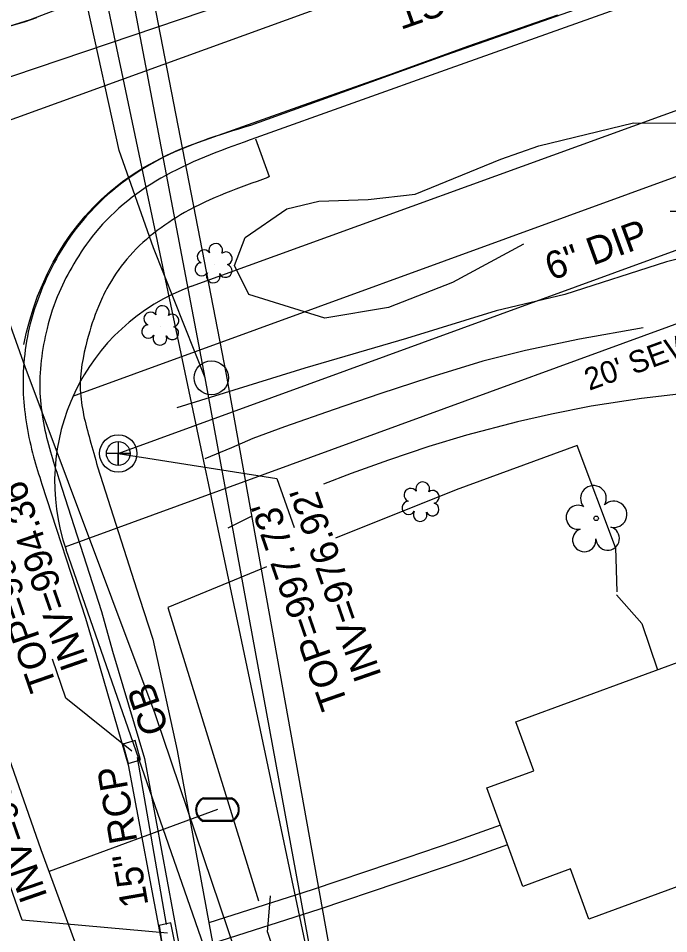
# Model space of a CAD drawing. Extents: x 1614427 to 1617186, y 896524 to 905462.
# Drawn here: x 1616382.3 to 1616476.2, y 903503 to 903635.2 of the extents above; entities that cross this region are included whole.
import ezdxf

# ---------------------------------------------------------------- set-up
doc = ezdxf.new("R2010")
doc.units = 0
for name, color, linetype in [('Exist Building', 7, 'Continuous'), ('Exist Horizontal Alignment', 7, 'Continuous'), ('Exist Other Culture Area Outline', 7, 'Continuous'), ('Exist Other Culture Fence Line', 7, 'Continuous'), ('Exist Other Culture Gate', 7, 'Continuous'), ('Exist Right of Way Easement Line', 7, 'Continuous'), ('Exist Right of Way Easement Line Text', 7, 'Continuous'), ('Exist Right of Way Line', 7, 'Continuous'), ('Exist Roads Curbs', 7, 'Continuous'), ('Exist Roads EOP', 7, 'Continuous'), ('Exist Roads EOP Other', 7, 'Continuous'), ('Exist Roads EOP Text', 7, 'Continuous'), ('Exist Roads Soil', 7, 'Continuous'), ('Exist Structure Minor Catch Basin', 7, 'Continuous'), ('Exist Structure Minor Catch Basin Leader', 7, 'Continuous'), ('Exist Structure Minor Catch Basin Text', 7, 'Continuous'), ('Exist Structure Minor Catch Basin Top Elevation', 7, 'Continuous'), ('Exist Structure Minor Pipes RCP 15 Inch', 7, 'Continuous'), ('Exist Structure Minor Pipes RCP 15 Inch Invert', 7, 'Continuous'), ('Exist Structure Minor Pipes RCP 15 Inch Text', 7, 'Continuous'), ('Exist Utilities Other Pole CELL', 7, 'Continuous'), ('Exist Utilities Sanitary Sewer Manhole CELL', 7, 'Continuous'), ('Exist Utilities Sanitary Sewer Manhole Leader', 7, 'Continuous'), ('Exist Utilities Sanitary Sewer Manhole Text', 7, 'Continuous'), ('Exist Utilities Sanitary Sewer UG Line', 7, 'Continuous'), ('Exist Utilities Sanitary Sewer UG Line Invert Elevation', 7, 'Continuous'), ('Exist Utilities Sanitary Sewer UG Line Text', 7, 'Continuous'), ('Exist Utilities Telephone UG FO SUE LOS B', 7, 'Continuous'), ('Exist Utilities Telephone UG FO SUE LOS D', 7, 'Continuous'), ('Exist Utilities TV UG FO Cable SUE LOS B', 7, 'Continuous'), ('Exist Utilities TV UG FO Cable SUE LOS D', 7, 'Continuous'), ('Exist Utilities Water Meter CELL', 7, 'Continuous'), ('Exist Utilities Water UG Line SUE LOS B', 7, 'Continuous'), ('Exist Vegetation Shrub CELL', 7, 'Continuous'), ('Exist Vegetation Tree CELL', 7, 'Continuous'), ('Exist Vegetation Woods Line', 7, 'Continuous')]:
    doc.layers.add(name, color=color, linetype=linetype)

# ---------------------------------------------------------------- blocks, each defined once
blk = doc.blocks.new('EXIST UTILITIES SANITARY SEWER MANHOLE')
at = {"layer": 'Exist Utilities Sanitary Sewer Manhole CELL'}
blk.add_lwpolyline([(0, 0.03425), (0, -0.03425), (0, 0), (0.03425, 0), (-0.03425, 0)], dxfattribs=at)
for radius in [0.05389, 0.03425]:
    blk.add_circle((0, 0), radius, dxfattribs=at)
blk = doc.blocks.new('EXIST UTILITIES WATER METER')
at = {"layer": 'Exist Utilities Water Meter CELL'}
blk.add_line((0, 0), (0, 0), dxfattribs=at)
for points in [[(-0.0408, 0.034), (0.0408, 0.034)], [(-0.0408, 0.0312), (0.0408, 0.0312)], [(0.0408, -0.0312), (-0.0413, -0.0312)], [(0.0408, -0.034), (-0.0413, -0.034)]]:
    blk.add_lwpolyline(points, dxfattribs=at)
for centre, radius, start, end in [((-0.0261, -0.0001), 0.0371, 113.178, 245.9794), ((-0.0259, -0.0001), 0.0347, 115.3009, 243.7824), ((0.0259, 0), 0.0371, 293.6483, 66.3084), ((0.0261, 0), 0.0345, 295.1272, 64.8728)]:
    blk.add_arc(centre, radius, start, end, dxfattribs=at)

msp = doc.modelspace()

# ---------------------------------------------------------------- linework, layer by layer
at = {"layer": 'Exist Building'}
msp.add_lwpolyline([(1616505.37, 903521.27), (1616502.73, 903520.3), (1616503.12, 903519.21), (1616464.68, 903505.13), (1616462.02, 903512.38), (1616455.15, 903509.86), (1616449.95, 903524.07), (1616456.72, 903526.55), (1616454.12, 903533.64), (1616480.87, 903543.44), (1616480.54, 903544.32), (1616491.93, 903548.49), (1616492.25, 903547.63), (1616496.91, 903549.34)], dxfattribs=at)
at = {"layer": 'Exist Horizontal Alignment'}
msp.add_line((1616340.93, 903605.93), (1616526.35, 903673.17), dxfattribs=at)
msp.add_line((1616340.93, 903605.93), (1616526.35, 903673.17), dxfattribs=at)
at = {"layer": 'Exist Other Culture Area Outline'}
for points in [[(1616451.92, 903518.69), (1616445.2, 903516.28), (1616436.15, 903513.22), (1616424.73, 903509.37), (1616409.8, 903504.59)], [(1616452.95, 903515.87), (1616446.19, 903513.45), (1616437.11, 903510.38), (1616425.67, 903506.52), (1616410.35, 903501.62)]]:
    msp.add_lwpolyline(points, dxfattribs=at)
at = {"layer": 'Exist Other Culture Fence Line'}
msp.add_line((1616472.36, 903547.79), (1616474.58, 903541.13), dxfattribs=at)
for points in [[(1616572.91, 903628.18), (1616564.21, 903625.69), (1616557.86, 903623.87), (1616549.37, 903621.59), (1616542.69, 903619.31), (1616531.55, 903615.59), (1616524.44, 903613.58), (1616517.86, 903611.96), (1616513.04, 903610.8), (1616507.24, 903608.97), (1616496.07, 903605.56), (1616484.35, 903602.15), (1616475.89, 903600.04), (1616461.24, 903595.28), (1616451.31, 903592.92), (1616438.36, 903588.93), (1616423.69, 903584.65), (1616405.19, 903578.96)], [(1616468.53, 903558.78), (1616463.02, 903573.52), (1616445.53, 903567.12), (1616428.08, 903560.12)], [(1616418.13, 903556), (1616403.89, 903550.11), (1616416.97, 903507.78)], [(1616418.3, 903503.27), (1616425.66, 903480.85), (1616434.72, 903450.26), (1616469.04, 903462.52), (1616499.54, 903473.23), (1616524.45, 903482.31), (1616513.56, 903511.28)]]:
    msp.add_lwpolyline(points, dxfattribs=at)
at = {"layer": 'Exist Other Culture Gate'}
msp.add_line((1616418.3, 903503.27), (1616418.73, 903508.5), dxfattribs=at)
for points in [[(1616468.53, 903558.78), (1616468.71, 903552.36)], [(1616472.36, 903547.79), (1616468.69, 903551.97)]]:
    msp.add_lwpolyline(points, dxfattribs=at)
at = {"layer": 'Exist Right of Way Easement Line'}
for p, q in [((1616390.19, 903580.61), (1616545.12, 903637.08)), ((1616389.05, 903558.9), (1616562.68, 903622.19))]:
    msp.add_line(p, q, dxfattribs=at)
msp.add_arc((1616417.55, 903568.29), 30, 109.9333, 199.1768, dxfattribs=at)
at = {"layer": 'Exist Right of Way Line'}
for p, q in [((1616010.65, 905462.23), (1616993.32, 900797.76)), ((1616407.32, 903596.49), (1616537.09, 903643.56))]:
    msp.add_line(p, q, dxfattribs=at)
msp.add_lwpolyline([(1616569.57, 903039.85), (1616389.21, 903558.44)], dxfattribs=at)
at = {"layer": 'Exist Roads Curbs'}
for points in [[(1616522.28, 903655.67), (1616483.74, 903641.89), (1616444.61, 903627.92), (1616416.59, 903617.9)], [(1616388.16, 903568.68), (1616394.31, 903549.56), (1616395.9, 903543.84), (1616400.51, 903528.3), (1616405.44, 903501.75), (1616409.55, 903479.29), (1616413.51, 903459.08), (1616414.52, 903456.07), (1616428.39, 903416.8), (1616436.43, 903393.84), (1616437.08, 903391.77)]]:
    msp.add_lwpolyline(points, dxfattribs=at)
msp.add_spline([(1616416.59, 903617.9), (1616403.61, 903612.49), (1616393.39, 903604.2), (1616390.31, 903599.71), (1616388.18, 903595.6), (1616386.45, 903590.39), (1616385.42, 903581.08), (1616386.94, 903572.59), (1616388.16, 903568.68)], degree=3, dxfattribs=at)
at = {"layer": 'Exist Roads EOP'}
for points in [[(1616273.35, 903855.36), (1616287.12, 903815.79), (1616301.21, 903775.08), (1616315.66, 903733.58), (1616330.46, 903693.74), (1616345.85, 903651.77), (1616353.93, 903639.77), (1616364.52, 903633.91), (1616370.25, 903632.83), (1616375.59, 903632.98), (1616380.35, 903633.82), (1616384.07, 903635.01), (1616390.61, 903637.51), (1616396.32, 903640.17), (1616405.35, 903644.69), (1616422.2, 903653.39)], [(1616521.59, 903657.43), (1616483.18, 903643.55), (1616483.16, 903643.61), (1616444.03, 903629.83), (1616415.81, 903619.72)], [(1616385.69, 903567.93), (1616392.01, 903548.56), (1616393.6, 903543.19), (1616398.15, 903527.41), (1616403.11, 903501.03), (1616407.24, 903478.89), (1616411.26, 903458.39), (1616412.38, 903455.21), (1616426.08, 903416.1), (1616434.07, 903392.9), (1616445.15, 903361.96), (1616458.31, 903324.81), (1616466.23, 903302.17), (1616474.95, 903277.55), (1616483.43, 903253.56), (1616487.42, 903242.35), (1616490.65, 903233.12), (1616499.86, 903207.54), (1616504.27, 903194.93)]]:
    msp.add_lwpolyline(points, dxfattribs=at)
msp.add_spline([(1616415.81, 903619.72), (1616402.39, 903614.65), (1616391.6, 903606), (1616388.11, 903601.01), (1616385.81, 903596.35), (1616384.03, 903591.09), (1616383.02, 903580.93), (1616384.51, 903571.87), (1616385.69, 903567.93)], degree=3, dxfattribs=at)
at = {"layer": 'Exist Roads EOP Other'}
for points in [[(1616383.11, 903588.08), (1616383.49, 903589.85), (1616383.94, 903591.6), (1616384.47, 903593.33), (1616385.08, 903595.04), (1616385.77, 903596.71), (1616386.52, 903598.35), (1616387.35, 903599.96), (1616388.25, 903601.53), (1616388.91, 903602.6), (1616389.86, 903603.99), (1616390.88, 903605.33), (1616391.96, 903606.62), (1616393.09, 903607.85), (1616394.29, 903609.04), (1616395.54, 903610.16), (1616396.84, 903611.22), (1616397.36, 903611.62), (1616398.9, 903612.67), (1616400.48, 903613.66), (1616402.1, 903614.57), (1616403.75, 903615.42), (1616405.45, 903616.19), (1616407.01, 903616.83), (1616414.04, 903619.32), (1616423.39, 903622.62), (1616435.93, 903627.07), (1616447.35, 903631.19), (1616460.21, 903635.69)], [(1616384.94, 903635.22), (1616383.12, 903634.62), (1616381.28, 903634.09)], [(1616416.53, 903617.78), (1616418.54, 903612.35), (1616418.34, 903612.18)], [(1616393.75, 903570.42), (1616399.81, 903551.47), (1616401.7, 903545.55), (1616405.22, 903529.49), (1616410.2, 903502.55), (1616414.5, 903479.85), (1616418.28, 903460.57), (1616419.24, 903457.77), (1616433.14, 903418.35), (1616440.08, 903398.17), (1616445.72, 903389.9), (1616453.5, 903367.66), (1616454.37, 903357.69), (1616465.19, 903327.22), (1616473.11, 903304.82), (1616479.64, 903286.51), (1616485.17, 903278.34), (1616491.89, 903259.49), (1616492.83, 903249.31), (1616495.45, 903241.87), (1616500.95, 903233.55), (1616508.16, 903214.09), (1616509.03, 903203.96)]]:
    msp.add_lwpolyline(points, dxfattribs=at)
msp.add_spline([(1616418.34, 903612.18), (1616406.31, 903607.12), (1616397.97, 903600.4), (1616395.1, 903596.18), (1616393.86, 903593.58), (1616392.26, 903588.77), (1616391.25, 903581.54), (1616392.64, 903574.35), (1616393.75, 903570.42)], degree=3, dxfattribs=at)
at = {"layer": 'Exist Roads Soil'}
for points in [[(1616472.55, 903590.47), (1616463.36, 903588.83), (1616455.54, 903587.21), (1616449.39, 903585.67), (1616441.71, 903583.31), (1616434.51, 903580.97), (1616427.92, 903578.72), (1616420.73, 903576.2), (1616416.16, 903574.51), (1616413.07, 903573.19), (1616409.25, 903571.6)], [(1616499.67, 903572.5), (1616498.59, 903574.77), (1616497.54, 903576.52), (1616496.43, 903577.96), (1616495.38, 903578.86), (1616493.21, 903580.08), (1616491.58, 903580.65), (1616489.07, 903581.25), (1616486.53, 903581.51), (1616483.91, 903581.53), (1616480.9, 903581.3), (1616472.29, 903580.3), (1616465.03, 903579.16), (1616459.27, 903578.05), (1616454.38, 903576.9), (1616447.04, 903575.01), (1616441.58, 903573.34), (1616435.76, 903571.37), (1616430.37, 903569.45), (1616426.35, 903567.9)], [(1616415.91, 903563.28), (1616412.54, 903561.58)]]:
    msp.add_lwpolyline(points, dxfattribs=at)
at = {"layer": 'Exist Structure Minor Catch Basin'}
for points in [[(1616399.18, 903530.92), (1616397.39, 903530.39), (1616398.14, 903527.62), (1616399.93, 903528.12), (1616399.18, 903530.92)], [(1616404.33, 903504.58), (1616402.63, 903504.21), (1616403.08, 903501.38), (1616404.91, 903501.73), (1616404.33, 903504.58)]]:
    msp.add_lwpolyline(points, dxfattribs=at)
at = {"layer": 'Exist Structure Minor Catch Basin Leader'}
for points in [[(1616398.71, 903529.4), (1616389.18, 903537.02), (1616387.21, 903542.68)], [(1616403.83, 903503.1), (1616382.84, 903504.97), (1616380.87, 903510.64)]]:
    msp.add_lwpolyline(points, dxfattribs=at)
at = {"layer": 'Exist Structure Minor Pipes RCP 15 Inch'}
msp.add_line((1616399.45, 903528.48), (1616403.65, 903504.38), dxfattribs=at)
msp.add_line((1616399.45, 903528.48), (1616403.65, 903504.38), dxfattribs=at)
at = {"layer": 'Exist Utilities Other Pole CELL'}
msp.add_circle((1616410.17, 903583.27), 2.46, dxfattribs=at)
at = {"layer": 'Exist Utilities Sanitary Sewer Manhole Leader'}
msp.add_lwpolyline([(1616396.73, 903572.35), (1616419.64, 903568.72), (1616422.13, 903561.66)], dxfattribs=at)
at = {"layer": 'Exist Utilities Sanitary Sewer UG Line'}
msp.add_line((1616396.73, 903572.35), (1616553.9, 903629.64), dxfattribs=at)
at = {"layer": 'Exist Utilities Telephone UG FO SUE LOS B'}
msp.add_lwpolyline([(1616519.36, 903185.77), (1616513.96, 903203.22), (1616503.76, 903233.09), (1616503.75, 903233.09), (1616489.07, 903279.68), (1616470.01, 903336.66), (1616452.34, 903386.43), (1616440.14, 903425.32), (1616426.94, 903455.24), (1616423.27, 903466.29), (1616413.77, 903500.18), (1616402.08, 903534.75), (1616383.28, 903584.85), (1616378.31, 903598.68), (1616360.02, 903639.24), (1616356.39, 903655.99), (1616340.68, 903699.57), (1616327.33, 903739.18), (1616327.34, 903739.18), (1616313.72, 903781.55), (1616301.65, 903812.03), (1616292.8, 903840.69)], dxfattribs=at)
at = {"layer": 'Exist Utilities Telephone UG FO SUE LOS D'}
msp.add_line((1616436.43, 903449.85), (1616412.38, 903583.74), dxfattribs=at)
msp.add_lwpolyline([(1616412.38, 903583.74), (1616374.62, 903777.9), (1616326.11, 903996.08), (1616269.81, 904283.52), (1616224.71, 904447.92), (1616220.83, 904470.3)], dxfattribs=at)
at = {"layer": 'Exist Utilities TV UG FO Cable SUE LOS B'}
msp.add_lwpolyline([(1616409.28, 903583.28), (1616401.83, 903602.06), (1616396.84, 903616.07), (1616392.29, 903636.86), (1616392.86, 903647.11), (1616394.48, 903651.32), (1616413.7, 903673.44), (1616420.55, 903677.59), (1616453.53, 903688.22), (1616514.87, 903711.84), (1616526.07, 903715.66), (1616536.86, 903720.55), (1616545.52, 903724.83), (1616549.16, 903728.55), (1616549.91, 903729.9), (1616554.28, 903748.73), (1616554.29, 903750.67), (1616552.37, 903762.47), (1616557.09, 903779.98), (1616577.36, 903795.05), (1616590.41, 903803.23)], dxfattribs=at)
at = {"layer": 'Exist Utilities TV UG FO Cable SUE LOS D'}
msp.add_lwpolyline([(1616615.13, 902920.57), (1616559.6, 903084.29), (1616508.29, 903236.97), (1616433.95, 903449.2), (1616409.28, 903583.28), (1616372.35, 903777.82), (1616323.57, 903995.2), (1616266.96, 904282.87), (1616220.39, 904446.95), (1616216.24, 904469.3), (1616198.7, 904563.75), (1616189.79, 904725.95), (1616160.9, 904944.94), (1616137.72, 905120.69)], dxfattribs=at)
at = {"layer": 'Exist Utilities Water UG Line SUE LOS B'}
msp.add_line((1616411.06, 903520.94), (1616386.76, 903512.03), dxfattribs=at)
for points in [[(1616526.94, 903118.95), (1616504.59, 903181.23), (1616480.02, 903252.46), (1616446.17, 903345), (1616411.28, 903445.17), (1616385.62, 903515.15), (1616350.02, 903616.87), (1616323.73, 903691.37), (1616291.21, 903786.26), (1616260.45, 903872.07), (1616224.66, 903974.02), (1616192.08, 904066.13), (1616173.94, 904118.11), (1616130.42, 904237.78), (1616097.26, 904331.65), (1616083.48, 904374.45), (1616069.85, 904420.53), (1616059.14, 904458.49), (1616050.85, 904496.39), (1616045.84, 904527.76), (1616030.28, 904669.9)], [(1616350.21, 903616.94), (1616374.62, 903624.54), (1616426.35, 903642.07), (1616478.57, 903660.36), (1616520.74, 903675.61), (1616534.8, 903680.84), (1616536.9, 903682.38), (1616549.12, 903691.48), (1616560.45, 903718.95), (1616573.2, 903736.65), (1616589.15, 903758.02), (1616604.81, 903760.79)]]:
    msp.add_lwpolyline(points, dxfattribs=at)
at = {"layer": 'Exist Vegetation Shrub CELL'}
for p, q in [((1616410.58, 903599.64), (1616410.58, 903599.64)), ((1616402.87, 903590.66), (1616402.87, 903590.66)), ((1616440.46, 903565.22), (1616440.46, 903565.22))]:
    msp.add_line(p, q, dxfattribs=at)
for centre, radius, start, end in [((1616410.81, 903601.68), 0.99, 334.8391, 200.4717), ((1616409.1, 903600.77), 0.968, 35.8908, 245.4216), ((1616412.26, 903600.51), 0.929, 284.4567, 126.0861), ((1616408.78, 903598.94), 0.955, 95.1099, 327.9534), ((1616412.22, 903598.71), 0.937, 204.9913, 73.4601), ((1616410.46, 903597.96), 0.984, 151.2797, 21.387), ((1616403.1, 903592.7), 0.99, 334.8391, 200.4717), ((1616401.39, 903591.78), 0.968, 35.8908, 245.4216), ((1616404.54, 903591.52), 0.929, 284.4567, 126.0861), ((1616401.07, 903589.95), 0.955, 95.1099, 327.9534), ((1616404.51, 903589.73), 0.937, 204.9913, 73.4601), ((1616402.74, 903588.97), 0.984, 151.2797, 21.387), ((1616440.69, 903567.26), 0.99, 334.8391, 200.4717), ((1616438.98, 903566.35), 0.968, 35.8908, 245.4216), ((1616442.13, 903566.09), 0.929, 284.4567, 126.0861), ((1616438.66, 903564.51), 0.955, 95.1099, 327.9534), ((1616442.1, 903564.29), 0.937, 204.9913, 73.4601), ((1616440.33, 903563.53), 0.984, 151.2797, 21.387)]:
    msp.add_arc(centre, radius, start, end, dxfattribs=at)
at = {"layer": 'Exist Vegetation Tree CELL'}
msp.add_line((1616465.74, 903562.99), (1616465.74, 903562.99), dxfattribs=at)
msp.add_circle((1616465.74, 903562.99), 0.326, dxfattribs=at)
for centre, radius, start, end in [((1616465.35, 903565.86), 1.86, 330.1651, 219.7134), ((1616463.13, 903563.14), 1.73, 62.6636, 279.3457), ((1616468.29, 903563.57), 1.9, 257.1011, 134.1999), ((1616467.41, 903560.09), 1.7, 181.2822, 74.56), ((1616464.03, 903559.87), 1.69, 111.5671, 6.231)]:
    msp.add_arc(centre, radius, start, end, dxfattribs=at)
at = {"layer": 'Exist Vegetation Woods Line'}
for points in [[(1616432.8, 903609.03), (1616439.6, 903609.78), (1616452, 903614.86), (1616457.45, 903616.76), (1616471.15, 903620.1), (1616477.81, 903620.04), (1616484.16, 903620.42), (1616496.78, 903617.93), (1616496.52, 903614.11), (1616487.2, 903608.39), (1616479.77, 903607.27), (1616476.43, 903607.29)], [(1616455.23, 903602.59), (1616444.98, 903597.01), (1616435.77, 903593.42), (1616426.54, 903591.87), (1616415.57, 903595.31), (1616413.5, 903599.49), (1616415.05, 903603.53), (1616421.05, 903607.65), (1616425.7, 903608.77), (1616432.8, 903609.03)]]:
    msp.add_lwpolyline(points, dxfattribs=at)

# ---------------------------------------------------------------- block references
at = {"layer": 'Exist Utilities Sanitary Sewer Manhole CELL', "xscale": 50, "yscale": 50}
msp.add_blockref('EXIST UTILITIES SANITARY SEWER MANHOLE', (1616396.73, 903572.35), dxfattribs=at)
at = {"layer": 'Exist Utilities Water Meter CELL', "xscale": 50, "yscale": 50}
msp.add_blockref('EXIST UTILITIES WATER METER', (1616411.06, 903520.94), dxfattribs=at)

# ---------------------------------------------------------------- texts
at = {"layer": 'Exist Right of Way Easement Line Text'}
msp.add_text("20' SEWER EASEMENT", height=3.2, rotation=20.0264, dxfattribs=at).set_placement((1616464.75, 903581.39))
at = {"layer": 'Exist Roads EOP Text'}
msp.add_text('SEA SHELL CT.', height=4, rotation=199.404, dxfattribs=at).set_placement((1616472.08, 903649.89))
at = {"layer": 'Exist Structure Minor Catch Basin Text'}
msp.add_text('CB', height=4, rotation=109.1768, dxfattribs=at).set_placement((1616404.09, 903532.53))
at = {"layer": 'Exist Structure Minor Catch Basin Top Elevation'}
msp.add_text("TOP=996.53'", height=4, rotation=109.1768, dxfattribs=at).set_placement((1616387.89, 903538.8))
at = {"layer": 'Exist Structure Minor Pipes RCP 15 Inch Invert'}
for s, p in [("INV=994.36'", (1616392.46, 903541.91)), ("INV=994.21'", (1616386.54, 903508.42))]:
    msp.add_text(s, height=4, rotation=109.1768, dxfattribs=at).set_placement(p)
at = {"layer": 'Exist Structure Minor Pipes RCP 15 Inch Text'}
msp.add_text('15" RCP', height=4, rotation=99.8866, dxfattribs=at).set_placement((1616401.1, 903507.19))
at = {"layer": 'Exist Utilities Sanitary Sewer Manhole Text'}
msp.add_text("TOP=997.73'", height=4, rotation=109.1768, dxfattribs=at).set_placement((1616429.96, 903536.17))
at = {"layer": 'Exist Utilities Sanitary Sewer UG Line Invert Elevation'}
msp.add_text("INV=976.92'", height=4, rotation=109.1768, dxfattribs=at).set_placement((1616434.8, 903540.29))
at = {"layer": 'Exist Utilities Sanitary Sewer UG Line Text'}
msp.add_text('6" DIP', height=4, rotation=20.0264, dxfattribs=at).set_placement((1616459.27, 903597.27))

doc.saveas('drawing.dxf')
